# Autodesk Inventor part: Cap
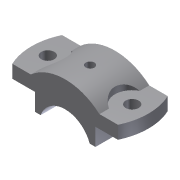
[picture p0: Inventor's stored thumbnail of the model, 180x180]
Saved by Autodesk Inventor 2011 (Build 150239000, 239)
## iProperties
Created: 2009-04
Part Number: Cap
Document SubType Name: Modeling
Designer: Sham
Density: 1 g/cm^3
Mass: 94.0133 g
Surface Area: 184.432 cm^2
Volume: 94.0133 cm^3
Author: Sham
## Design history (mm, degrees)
sketch "Sketch1"
  geometry: L1 (-48.857, 23)-(48.857, 23); L2 (48.857, -23)-(-48.857, -23); A1 r 54 centre (0, 0) between (-48.857, 23) and (-48.857, -23); A2 r 54 centre (0, 0) between (48.857, -23) and (48.857, 23); 1 further point
  constraints: 4 end point, 4 point on circle, 2 centre point, 2 coincident, 1 horizontal, 1 parallel, 1 other
  dimensions: "d3" = 54 radius of A1; "d4" = 54 radius of A2; "d5" = 46 distance between parallel lines of L2 L1; "d6" = 23 distance from line of point (0, 0) L1
extrude "Extrusion1" new body sketch "Sketch1" distance "d7" = 12; taper "d8" = 0 deg
sketch "Sketch3"
  geometry: L1 (20.906, 0)-(20.906, -16); L2 (76.906, -0.137)-(76.906, -16.137); L3 (20.906, -16)-(26.23, -16); L4 (71.532, -16.137)-(76.906, -16.137); L5 (76.906, -0.137)-(76.857, 12); L6 (97.714, 0)-(0, 0) reference; L7 (76.857, 12)-(80.606, 12); L8 (17.108, 12)-(20.906, 12); L9 (20.906, 12)-(20.906, 0); L10 (0, 12)-(97.714, 12) reference; A1 r 24 centre (48.857, -24) between (71.532, -16.137) and (26.23, -16); A2 r 48 centre (48.857, -24) between (80.606, 12) and (17.108, 12); 3 further points
  constraints: 16 end point, 4 point on circle, 3 parallel, 3 perpendicular, 2 centre point, 2 coincident, 2 vertical alignment, 1 collinear, 1 midpoint, 1 vertical, 2 other
  dimensions: "d17" = 48 diameter of A1; "d18" = 16 distance of L1.start L1.end; "d19" = 56 distance between parallel lines of L2 L1; "d21" = 8 vertical distance of A1.centre L1.end; "d22" = 48 radius of A2; "d23" = 0 distance from line of L6 L1.start; "d38" = 31.74902 distance of L7.end point (48.857, 12); "d39" = 28 distance from line of point (48.857, 12) L5
extrude "Extrusion2" join sketch "Sketch3" stored distance "d24" = 12; taper "d25" = 0 deg
sketch "Sketch4"
  geometry: 2 further points
  dimensions: "d26" = 78 distance of point (39, 0) point (-39, 0)
hole "Hole1" sketch "Sketch4" at (-39, 0), (39, 0) diameter "d28" = 12; stored, may be unused: countersink angle "d32" = 90 deg, drill point angle "d34" = 118 deg; dims "d29" = 6, "d30" = 4, "d31" = 2, "d33" = 8
sketch "Sketch5"
  geometry: L1 (-31.749, -23)-(-31.749, 23) reference; L2 (-31.749, 14.263)-(-31.749, -14.263); C1 r 6 at (-39, 0) reference; A1 r 16 centre (-39, 0) between (-31.749, -14.263) and (-31.749, 14.263)
  constraints: 2 end point, 2 point on circle, 1 centre point, 1 coincident, 1 collinear, 1 point on line
  dimensions: "d35" = 16 radius of A1
extrude "Extrusion3" cut sketch "Sketch5" distance "d36" = 12; taper "d37" = 0 deg
mirror "Mirror2"
workplane "Work Plane4"
sketch "Sketch6"
  geometry: L1 (-31.749, 0)-(31.749, 0) reference; 1 further point
  dimensions: "d40" = 23 distance from line of L1 point (0, 23)
hole "Hole2" sketch "Sketch6" at (0, 23) diameter "d41" = 6; stored, may be unused: countersink angle "d45" = 90 deg, drill point angle "d47" = 118 deg; dims "d42" = 6, "d43" = 8, "d44" = 16, "d46" = 8
body "Solid1"
